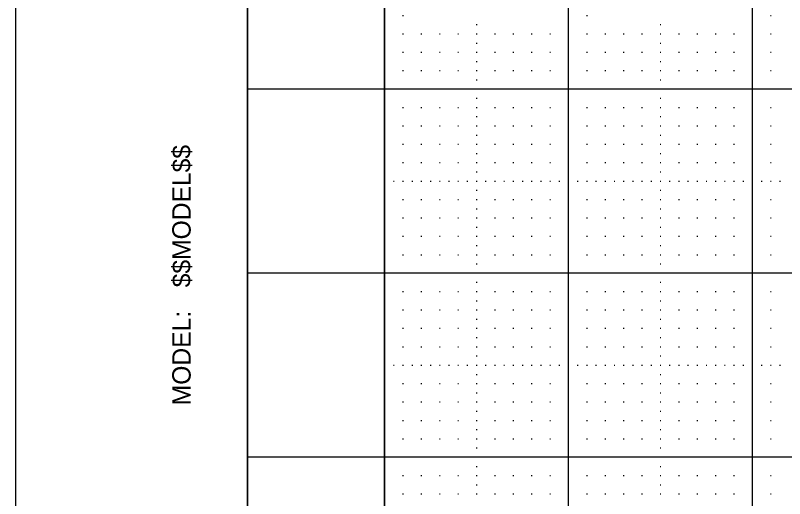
# Model space of a CAD drawing. Extents: x -1.3 to 32.1, y -0.2 to 20.7.
# Drawn here: x -1.263 to 2.92, y 5.068 to 7.693 of the extents above; entities that cross this region are included whole.
import ezdxf

# ---------------------------------------------------------------- set-up
doc = ezdxf.new("R2010")
doc.units = 0
for name, color, linetype in [('Level 1', 7, 'Continuous'), ('Level 37', 7, 'Continuous'), ('Level 4', 7, 'Continuous'), ('Level 5', 7, 'Continuous'), ('Level 62', 7, 'Continuous'), ('Level 63', 7, 'Continuous')]:
    doc.layers.add(name, color=color, linetype=linetype)

msp = doc.modelspace()

# ---------------------------------------------------------------- linework, layer by layer
at = {"layer": 'Level 1'}
msp.add_line((-0.001, -0.001), (-0.001, 20.545), dxfattribs=at)
at = {"layer": 'Level 37'}
msp.add_line((0.746, 0.6725), (0.746, 10.2935), dxfattribs=at)
at = {"layer": 'Level 4'}
for p, q in [((0.745, 0.672), (0.745, 10.293)), ((1.745, 0.672), (1.745, 10.293)), ((2.745, 0.293), (2.745, 10.293)), ((31.617, 7.293), (-0.001, 7.293)), ((31.617, 6.293), (-0.001, 6.293)), ((31.617, 5.293), (-0.001, 5.293))]:
    msp.add_line(p, q, dxfattribs=at)
at = {"layer": 'Level 5'}
for p, q in [((0.8425, 7.693), (0.8475, 7.693)), ((1.8425, 7.693), (1.8475, 7.693)), ((2.8425, 7.693), (2.8475, 7.693)), ((1.2425, 7.643), (1.2475, 7.643)), ((2.2425, 7.643), (2.2475, 7.643)), ((0.8425, 7.593), (0.8475, 7.593)), ((0.9425, 7.593), (0.9475, 7.593)), ((1.0425, 7.593), (1.0475, 7.593)), ((1.1425, 7.593), (1.1475, 7.593)), ((1.2425, 7.593), (1.2475, 7.593)), ((1.3425, 7.593), (1.3475, 7.593)), ((1.4425, 7.593), (1.4475, 7.593)), ((1.5425, 7.593), (1.5475, 7.593)), ((1.6425, 7.593), (1.6475, 7.593)), ((1.8425, 7.593), (1.8475, 7.593)), ((1.9425, 7.593), (1.9475, 7.593)), ((2.0425, 7.593), (2.0475, 7.593)), ((2.1425, 7.593), (2.1475, 7.593)), ((2.2425, 7.593), (2.2475, 7.593)), ((2.3425, 7.593), (2.3475, 7.593)), ((2.4425, 7.593), (2.4475, 7.593)), ((2.5425, 7.593), (2.5475, 7.593)), ((2.6425, 7.593), (2.6475, 7.593)), ((2.8425, 7.593), (2.8475, 7.593)), ((1.2425, 7.543), (1.2475, 7.543)), ((2.2425, 7.543), (2.2475, 7.543)), ((0.8425, 7.493), (0.8475, 7.493)), ((0.9425, 7.493), (0.9475, 7.493)), ((1.0425, 7.493), (1.0475, 7.493)), ((1.1425, 7.493), (1.1475, 7.493)), ((1.2425, 7.493), (1.2475, 7.493)), ((1.3425, 7.493), (1.3475, 7.493)), ((1.4425, 7.493), (1.4475, 7.493)), ((1.5425, 7.493), (1.5475, 7.493)), ((1.6425, 7.493), (1.6475, 7.493)), ((1.8425, 7.493), (1.8475, 7.493)), ((1.9425, 7.493), (1.9475, 7.493)), ((2.0425, 7.493), (2.0475, 7.493)), ((2.1425, 7.493), (2.1475, 7.493)), ((2.2425, 7.493), (2.2475, 7.493)), ((2.3425, 7.493), (2.3475, 7.493)), ((2.4425, 7.493), (2.4475, 7.493)), ((2.5425, 7.493), (2.5475, 7.493)), ((2.6425, 7.493), (2.6475, 7.493)), ((2.8425, 7.493), (2.8475, 7.493)), ((1.2425, 7.443), (1.2475, 7.443)), ((2.2425, 7.443), (2.2475, 7.443)), ((0.8425, 7.393), (0.8475, 7.393)), ((0.9425, 7.393), (0.9475, 7.393)), ((1.0425, 7.393), (1.0475, 7.393)), ((1.1425, 7.393), (1.1475, 7.393)), ((1.2425, 7.393), (1.2475, 7.393)), ((1.3425, 7.393), (1.3475, 7.393)), ((1.4425, 7.393), (1.4475, 7.393)), ((1.5425, 7.393), (1.5475, 7.393)), ((1.6425, 7.393), (1.6475, 7.393)), ((1.8425, 7.393), (1.8475, 7.393)), ((1.9425, 7.393), (1.9475, 7.393)), ((2.0425, 7.393), (2.0475, 7.393)), ((2.1425, 7.393), (2.1475, 7.393)), ((2.2425, 7.393), (2.2475, 7.393)), ((2.3425, 7.393), (2.3475, 7.393)), ((2.4425, 7.393), (2.4475, 7.393)), ((2.5425, 7.393), (2.5475, 7.393)), ((2.6425, 7.393), (2.6475, 7.393)), ((2.8425, 7.393), (2.8475, 7.393)), ((1.2425, 7.343), (1.2475, 7.343)), ((2.2425, 7.343), (2.2475, 7.343)), ((1.2425, 7.243), (1.2475, 7.243)), ((2.2425, 7.243), (2.2475, 7.243)), ((0.8425, 7.193), (0.8475, 7.193)), ((0.9425, 7.193), (0.9475, 7.193)), ((1.0425, 7.193), (1.0475, 7.193)), ((1.1425, 7.193), (1.1475, 7.193)), ((1.2425, 7.193), (1.2475, 7.193)), ((1.3425, 7.193), (1.3475, 7.193)), ((1.4425, 7.193), (1.4475, 7.193)), ((1.5425, 7.193), (1.5475, 7.193)), ((1.6425, 7.193), (1.6475, 7.193)), ((1.8425, 7.193), (1.8475, 7.193)), ((1.9425, 7.193), (1.9475, 7.193)), ((2.0425, 7.193), (2.0475, 7.193)), ((2.1425, 7.193), (2.1475, 7.193)), ((2.2425, 7.193), (2.2475, 7.193)), ((2.3425, 7.193), (2.3475, 7.193)), ((2.4425, 7.193), (2.4475, 7.193)), ((2.5425, 7.193), (2.5475, 7.193)), ((2.6425, 7.193), (2.6475, 7.193)), ((2.8425, 7.193), (2.8475, 7.193)), ((1.2425, 7.143), (1.2475, 7.143)), ((2.2425, 7.143), (2.2475, 7.143)), ((0.8425, 7.093), (0.8475, 7.093)), ((0.9425, 7.093), (0.9475, 7.093)), ((1.0425, 7.093), (1.0475, 7.093)), ((1.1425, 7.093), (1.1475, 7.093)), ((1.2425, 7.093), (1.2475, 7.093)), ((1.3425, 7.093), (1.3475, 7.093)), ((1.4425, 7.093), (1.4475, 7.093)), ((1.5425, 7.093), (1.5475, 7.093)), ((1.6425, 7.093), (1.6475, 7.093)), ((1.8425, 7.093), (1.8475, 7.093)), ((1.9425, 7.093), (1.9475, 7.093)), ((2.0425, 7.093), (2.0475, 7.093)), ((2.1425, 7.093), (2.1475, 7.093)), ((2.2425, 7.093), (2.2475, 7.093)), ((2.3425, 7.093), (2.3475, 7.093)), ((2.4425, 7.093), (2.4475, 7.093)), ((2.5425, 7.093), (2.5475, 7.093)), ((2.6425, 7.093), (2.6475, 7.093)), ((2.8425, 7.093), (2.8475, 7.093)), ((1.2425, 7.043), (1.2475, 7.043)), ((2.2425, 7.043), (2.2475, 7.043)), ((0.8425, 6.993), (0.8475, 6.993)), ((0.9425, 6.993), (0.9475, 6.993)), ((1.0425, 6.993), (1.0475, 6.993)), ((1.1425, 6.993), (1.1475, 6.993)), ((1.2425, 6.993), (1.2475, 6.993)), ((1.3425, 6.993), (1.3475, 6.993)), ((1.4425, 6.993), (1.4475, 6.993)), ((1.5425, 6.993), (1.5475, 6.993)), ((1.6425, 6.993), (1.6475, 6.993)), ((1.8425, 6.993), (1.8475, 6.993)), ((1.9425, 6.993), (1.9475, 6.993)), ((2.0425, 6.993), (2.0475, 6.993)), ((2.1425, 6.993), (2.1475, 6.993)), ((2.2425, 6.993), (2.2475, 6.993)), ((2.3425, 6.993), (2.3475, 6.993)), ((2.4425, 6.993), (2.4475, 6.993)), ((2.5425, 6.993), (2.5475, 6.993)), ((2.6425, 6.993), (2.6475, 6.993)), ((2.8425, 6.993), (2.8475, 6.993)), ((1.2425, 6.943), (1.2475, 6.943)), ((2.2425, 6.943), (2.2475, 6.943)), ((0.8425, 6.893), (0.8475, 6.893)), ((0.9425, 6.893), (0.9475, 6.893)), ((1.0425, 6.893), (1.0475, 6.893)), ((1.1425, 6.893), (1.1475, 6.893)), ((1.2425, 6.893), (1.2475, 6.893)), ((1.3425, 6.893), (1.3475, 6.893)), ((1.4425, 6.893), (1.4475, 6.893)), ((1.5425, 6.893), (1.5475, 6.893)), ((1.6425, 6.893), (1.6475, 6.893)), ((1.8425, 6.893), (1.8475, 6.893)), ((1.9425, 6.893), (1.9475, 6.893)), ((2.0425, 6.893), (2.0475, 6.893)), ((2.1425, 6.893), (2.1475, 6.893)), ((2.2425, 6.893), (2.2475, 6.893)), ((2.3425, 6.893), (2.3475, 6.893)), ((2.4425, 6.893), (2.4475, 6.893)), ((2.5425, 6.893), (2.5475, 6.893)), ((2.6425, 6.893), (2.6475, 6.893)), ((2.8425, 6.893), (2.8475, 6.893)), ((1.2425, 6.843), (1.2475, 6.843)), ((2.2425, 6.843), (2.2475, 6.843)), ((0.7925, 6.793), (0.7975, 6.793)), ((0.8425, 6.793), (0.8475, 6.793)), ((0.8925, 6.793), (0.8975, 6.793)), ((0.9425, 6.793), (0.9475, 6.793)), ((0.9925, 6.793), (0.9975, 6.793)), ((1.0425, 6.793), (1.0475, 6.793)), ((1.0925, 6.793), (1.0975, 6.793)), ((1.1425, 6.793), (1.1475, 6.793)), ((1.1925, 6.793), (1.1975, 6.793)), ((1.2425, 6.793), (1.2475, 6.793)), ((1.2925, 6.793), (1.2975, 6.793)), ((1.3425, 6.793), (1.3475, 6.793)), ((1.3925, 6.793), (1.3975, 6.793)), ((1.4425, 6.793), (1.4475, 6.793)), ((1.4925, 6.793), (1.4975, 6.793)), ((1.5425, 6.793), (1.5475, 6.793)), ((1.5925, 6.793), (1.5975, 6.793)), ((1.6425, 6.793), (1.6475, 6.793)), ((1.6925, 6.793), (1.6975, 6.793)), ((1.7925, 6.793), (1.7975, 6.793)), ((1.8425, 6.793), (1.8475, 6.793)), ((1.8925, 6.793), (1.8975, 6.793)), ((1.9425, 6.793), (1.9475, 6.793)), ((1.9925, 6.793), (1.9975, 6.793)), ((2.0425, 6.793), (2.0475, 6.793)), ((2.0925, 6.793), (2.0975, 6.793)), ((2.1425, 6.793), (2.1475, 6.793)), ((2.1925, 6.793), (2.1975, 6.793)), ((2.2425, 6.793), (2.2475, 6.793)), ((2.2925, 6.793), (2.2975, 6.793)), ((2.3425, 6.793), (2.3475, 6.793)), ((2.3925, 6.793), (2.3975, 6.793)), ((2.4425, 6.793), (2.4475, 6.793)), ((2.4925, 6.793), (2.4975, 6.793)), ((2.5425, 6.793), (2.5475, 6.793)), ((2.5925, 6.793), (2.5975, 6.793)), ((2.6425, 6.793), (2.6475, 6.793)), ((2.6925, 6.793), (2.6975, 6.793)), ((2.7925, 6.793), (2.7975, 6.793)), ((2.8425, 6.793), (2.8475, 6.793)), ((2.8925, 6.793), (2.8975, 6.793)), ((1.2425, 6.743), (1.2475, 6.743)), ((2.2425, 6.743), (2.2475, 6.743)), ((0.8425, 6.693), (0.8475, 6.693)), ((0.9425, 6.693), (0.9475, 6.693)), ((1.0425, 6.693), (1.0475, 6.693)), ((1.1425, 6.693), (1.1475, 6.693)), ((1.2425, 6.693), (1.2475, 6.693)), ((1.3425, 6.693), (1.3475, 6.693)), ((1.4425, 6.693), (1.4475, 6.693)), ((1.5425, 6.693), (1.5475, 6.693)), ((1.6425, 6.693), (1.6475, 6.693)), ((1.8425, 6.693), (1.8475, 6.693)), ((1.9425, 6.693), (1.9475, 6.693)), ((2.0425, 6.693), (2.0475, 6.693)), ((2.1425, 6.693), (2.1475, 6.693)), ((2.2425, 6.693), (2.2475, 6.693)), ((2.3425, 6.693), (2.3475, 6.693)), ((2.4425, 6.693), (2.4475, 6.693)), ((2.5425, 6.693), (2.5475, 6.693)), ((2.6425, 6.693), (2.6475, 6.693)), ((2.8425, 6.693), (2.8475, 6.693)), ((1.2425, 6.643), (1.2475, 6.643)), ((2.2425, 6.643), (2.2475, 6.643)), ((0.8425, 6.593), (0.8475, 6.593)), ((0.9425, 6.593), (0.9475, 6.593)), ((1.0425, 6.593), (1.0475, 6.593)), ((1.1425, 6.593), (1.1475, 6.593)), ((1.2425, 6.593), (1.2475, 6.593)), ((1.3425, 6.593), (1.3475, 6.593)), ((1.4425, 6.593), (1.4475, 6.593)), ((1.5425, 6.593), (1.5475, 6.593)), ((1.6425, 6.593), (1.6475, 6.593)), ((1.8425, 6.593), (1.8475, 6.593)), ((1.9425, 6.593), (1.9475, 6.593)), ((2.0425, 6.593), (2.0475, 6.593)), ((2.1425, 6.593), (2.1475, 6.593)), ((2.2425, 6.593), (2.2475, 6.593)), ((2.3425, 6.593), (2.3475, 6.593)), ((2.4425, 6.593), (2.4475, 6.593)), ((2.5425, 6.593), (2.5475, 6.593)), ((2.6425, 6.593), (2.6475, 6.593)), ((2.8425, 6.593), (2.8475, 6.593)), ((1.2425, 6.543), (1.2475, 6.543)), ((2.2425, 6.543), (2.2475, 6.543)), ((0.8425, 6.493), (0.8475, 6.493)), ((0.9425, 6.493), (0.9475, 6.493)), ((1.0425, 6.493), (1.0475, 6.493)), ((1.1425, 6.493), (1.1475, 6.493)), ((1.2425, 6.493), (1.2475, 6.493)), ((1.3425, 6.493), (1.3475, 6.493)), ((1.4425, 6.493), (1.4475, 6.493)), ((1.5425, 6.493), (1.5475, 6.493)), ((1.6425, 6.493), (1.6475, 6.493)), ((1.8425, 6.493), (1.8475, 6.493)), ((1.9425, 6.493), (1.9475, 6.493)), ((2.0425, 6.493), (2.0475, 6.493)), ((2.1425, 6.493), (2.1475, 6.493)), ((2.2425, 6.493), (2.2475, 6.493)), ((2.3425, 6.493), (2.3475, 6.493)), ((2.4425, 6.493), (2.4475, 6.493)), ((2.5425, 6.493), (2.5475, 6.493)), ((2.6425, 6.493), (2.6475, 6.493)), ((2.8425, 6.493), (2.8475, 6.493)), ((1.2425, 6.443), (1.2475, 6.443)), ((2.2425, 6.443), (2.2475, 6.443)), ((0.8425, 6.393), (0.8475, 6.393)), ((0.9425, 6.393), (0.9475, 6.393)), ((1.0425, 6.393), (1.0475, 6.393)), ((1.1425, 6.393), (1.1475, 6.393)), ((1.2425, 6.393), (1.2475, 6.393)), ((1.3425, 6.393), (1.3475, 6.393)), ((1.4425, 6.393), (1.4475, 6.393)), ((1.5425, 6.393), (1.5475, 6.393)), ((1.6425, 6.393), (1.6475, 6.393)), ((1.8425, 6.393), (1.8475, 6.393)), ((1.9425, 6.393), (1.9475, 6.393)), ((2.0425, 6.393), (2.0475, 6.393)), ((2.1425, 6.393), (2.1475, 6.393)), ((2.2425, 6.393), (2.2475, 6.393)), ((2.3425, 6.393), (2.3475, 6.393)), ((2.4425, 6.393), (2.4475, 6.393)), ((2.5425, 6.393), (2.5475, 6.393)), ((2.6425, 6.393), (2.6475, 6.393)), ((2.8425, 6.393), (2.8475, 6.393)), ((1.2425, 6.343), (1.2475, 6.343)), ((2.2425, 6.343), (2.2475, 6.343)), ((1.2425, 6.243), (1.2475, 6.243)), ((2.2425, 6.243), (2.2475, 6.243)), ((0.8425, 6.193), (0.8475, 6.193)), ((0.9425, 6.193), (0.9475, 6.193)), ((1.0425, 6.193), (1.0475, 6.193)), ((1.1425, 6.193), (1.1475, 6.193)), ((1.2425, 6.193), (1.2475, 6.193)), ((1.3425, 6.193), (1.3475, 6.193)), ((1.4425, 6.193), (1.4475, 6.193)), ((1.5425, 6.193), (1.5475, 6.193)), ((1.6425, 6.193), (1.6475, 6.193)), ((1.8425, 6.193), (1.8475, 6.193)), ((1.9425, 6.193), (1.9475, 6.193)), ((2.0425, 6.193), (2.0475, 6.193)), ((2.1425, 6.193), (2.1475, 6.193)), ((2.2425, 6.193), (2.2475, 6.193)), ((2.3425, 6.193), (2.3475, 6.193)), ((2.4425, 6.193), (2.4475, 6.193)), ((2.5425, 6.193), (2.5475, 6.193)), ((2.6425, 6.193), (2.6475, 6.193)), ((2.8425, 6.193), (2.8475, 6.193)), ((1.2425, 6.143), (1.2475, 6.143)), ((2.2425, 6.143), (2.2475, 6.143)), ((0.8425, 6.093), (0.8475, 6.093)), ((0.9425, 6.093), (0.9475, 6.093)), ((1.0425, 6.093), (1.0475, 6.093)), ((1.1425, 6.093), (1.1475, 6.093)), ((1.2425, 6.093), (1.2475, 6.093)), ((1.3425, 6.093), (1.3475, 6.093)), ((1.4425, 6.093), (1.4475, 6.093)), ((1.5425, 6.093), (1.5475, 6.093)), ((1.6425, 6.093), (1.6475, 6.093)), ((1.8425, 6.093), (1.8475, 6.093)), ((1.9425, 6.093), (1.9475, 6.093)), ((2.0425, 6.093), (2.0475, 6.093)), ((2.1425, 6.093), (2.1475, 6.093)), ((2.2425, 6.093), (2.2475, 6.093)), ((2.3425, 6.093), (2.3475, 6.093)), ((2.4425, 6.093), (2.4475, 6.093)), ((2.5425, 6.093), (2.5475, 6.093)), ((2.6425, 6.093), (2.6475, 6.093)), ((2.8425, 6.093), (2.8475, 6.093)), ((1.2425, 6.043), (1.2475, 6.043)), ((2.2425, 6.043), (2.2475, 6.043)), ((0.8425, 5.993), (0.8475, 5.993)), ((0.9425, 5.993), (0.9475, 5.993)), ((1.0425, 5.993), (1.0475, 5.993)), ((1.1425, 5.993), (1.1475, 5.993)), ((1.2425, 5.993), (1.2475, 5.993)), ((1.3425, 5.993), (1.3475, 5.993)), ((1.4425, 5.993), (1.4475, 5.993)), ((1.5425, 5.993), (1.5475, 5.993)), ((1.6425, 5.993), (1.6475, 5.993)), ((1.8425, 5.993), (1.8475, 5.993)), ((1.9425, 5.993), (1.9475, 5.993)), ((2.0425, 5.993), (2.0475, 5.993)), ((2.1425, 5.993), (2.1475, 5.993)), ((2.2425, 5.993), (2.2475, 5.993)), ((2.3425, 5.993), (2.3475, 5.993)), ((2.4425, 5.993), (2.4475, 5.993)), ((2.5425, 5.993), (2.5475, 5.993)), ((2.6425, 5.993), (2.6475, 5.993)), ((2.8425, 5.993), (2.8475, 5.993)), ((1.2425, 5.943), (1.2475, 5.943)), ((2.2425, 5.943), (2.2475, 5.943)), ((0.8425, 5.893), (0.8475, 5.893)), ((0.9425, 5.893), (0.9475, 5.893)), ((1.0425, 5.893), (1.0475, 5.893)), ((1.1425, 5.893), (1.1475, 5.893)), ((1.2425, 5.893), (1.2475, 5.893)), ((1.3425, 5.893), (1.3475, 5.893)), ((1.4425, 5.893), (1.4475, 5.893)), ((1.5425, 5.893), (1.5475, 5.893)), ((1.6425, 5.893), (1.6475, 5.893)), ((1.8425, 5.893), (1.8475, 5.893)), ((1.9425, 5.893), (1.9475, 5.893)), ((2.0425, 5.893), (2.0475, 5.893)), ((2.1425, 5.893), (2.1475, 5.893)), ((2.2425, 5.893), (2.2475, 5.893)), ((2.3425, 5.893), (2.3475, 5.893)), ((2.4425, 5.893), (2.4475, 5.893)), ((2.5425, 5.893), (2.5475, 5.893)), ((2.6425, 5.893), (2.6475, 5.893)), ((2.8425, 5.893), (2.8475, 5.893)), ((1.2425, 5.843), (1.2475, 5.843)), ((2.2425, 5.843), (2.2475, 5.843)), ((0.7925, 5.793), (0.7975, 5.793)), ((0.8425, 5.793), (0.8475, 5.793)), ((0.8925, 5.793), (0.8975, 5.793)), ((0.9425, 5.793), (0.9475, 5.793)), ((0.9925, 5.793), (0.9975, 5.793)), ((1.0425, 5.793), (1.0475, 5.793)), ((1.0925, 5.793), (1.0975, 5.793)), ((1.1425, 5.793), (1.1475, 5.793)), ((1.1925, 5.793), (1.1975, 5.793)), ((1.2425, 5.793), (1.2475, 5.793)), ((1.2925, 5.793), (1.2975, 5.793)), ((1.3425, 5.793), (1.3475, 5.793)), ((1.3925, 5.793), (1.3975, 5.793)), ((1.4425, 5.793), (1.4475, 5.793)), ((1.4925, 5.793), (1.4975, 5.793)), ((1.5425, 5.793), (1.5475, 5.793)), ((1.5925, 5.793), (1.5975, 5.793)), ((1.6425, 5.793), (1.6475, 5.793)), ((1.6925, 5.793), (1.6975, 5.793)), ((1.7925, 5.793), (1.7975, 5.793)), ((1.8425, 5.793), (1.8475, 5.793)), ((1.8925, 5.793), (1.8975, 5.793)), ((1.9425, 5.793), (1.9475, 5.793)), ((1.9925, 5.793), (1.9975, 5.793)), ((2.0425, 5.793), (2.0475, 5.793)), ((2.0925, 5.793), (2.0975, 5.793)), ((2.1425, 5.793), (2.1475, 5.793)), ((2.1925, 5.793), (2.1975, 5.793)), ((2.2425, 5.793), (2.2475, 5.793)), ((2.2925, 5.793), (2.2975, 5.793)), ((2.3425, 5.793), (2.3475, 5.793)), ((2.3925, 5.793), (2.3975, 5.793)), ((2.4425, 5.793), (2.4475, 5.793)), ((2.4925, 5.793), (2.4975, 5.793)), ((2.5425, 5.793), (2.5475, 5.793)), ((2.5925, 5.793), (2.5975, 5.793)), ((2.6425, 5.793), (2.6475, 5.793)), ((2.6925, 5.793), (2.6975, 5.793)), ((2.7925, 5.793), (2.7975, 5.793)), ((2.8425, 5.793), (2.8475, 5.793)), ((2.8925, 5.793), (2.8975, 5.793)), ((1.2425, 5.743), (1.2475, 5.743)), ((2.2425, 5.743), (2.2475, 5.743)), ((0.8425, 5.693), (0.8475, 5.693)), ((0.9425, 5.693), (0.9475, 5.693)), ((1.0425, 5.693), (1.0475, 5.693)), ((1.1425, 5.693), (1.1475, 5.693)), ((1.2425, 5.693), (1.2475, 5.693)), ((1.3425, 5.693), (1.3475, 5.693)), ((1.4425, 5.693), (1.4475, 5.693)), ((1.5425, 5.693), (1.5475, 5.693)), ((1.6425, 5.693), (1.6475, 5.693)), ((1.8425, 5.693), (1.8475, 5.693)), ((1.9425, 5.693), (1.9475, 5.693)), ((2.0425, 5.693), (2.0475, 5.693)), ((2.1425, 5.693), (2.1475, 5.693)), ((2.2425, 5.693), (2.2475, 5.693)), ((2.3425, 5.693), (2.3475, 5.693)), ((2.4425, 5.693), (2.4475, 5.693)), ((2.5425, 5.693), (2.5475, 5.693)), ((2.6425, 5.693), (2.6475, 5.693)), ((2.8425, 5.693), (2.8475, 5.693)), ((1.2425, 5.643), (1.2475, 5.643)), ((2.2425, 5.643), (2.2475, 5.643)), ((0.8425, 5.593), (0.8475, 5.593)), ((0.9425, 5.593), (0.9475, 5.593)), ((1.0425, 5.593), (1.0475, 5.593)), ((1.1425, 5.593), (1.1475, 5.593)), ((1.2425, 5.593), (1.2475, 5.593)), ((1.3425, 5.593), (1.3475, 5.593)), ((1.4425, 5.593), (1.4475, 5.593)), ((1.5425, 5.593), (1.5475, 5.593)), ((1.6425, 5.593), (1.6475, 5.593)), ((1.8425, 5.593), (1.8475, 5.593)), ((1.9425, 5.593), (1.9475, 5.593)), ((2.0425, 5.593), (2.0475, 5.593)), ((2.1425, 5.593), (2.1475, 5.593)), ((2.2425, 5.593), (2.2475, 5.593)), ((2.3425, 5.593), (2.3475, 5.593)), ((2.4425, 5.593), (2.4475, 5.593)), ((2.5425, 5.593), (2.5475, 5.593)), ((2.6425, 5.593), (2.6475, 5.593)), ((2.8425, 5.593), (2.8475, 5.593)), ((1.2425, 5.543), (1.2475, 5.543)), ((2.2425, 5.543), (2.2475, 5.543)), ((0.8425, 5.493), (0.8475, 5.493)), ((0.9425, 5.493), (0.9475, 5.493)), ((1.0425, 5.493), (1.0475, 5.493)), ((1.1425, 5.493), (1.1475, 5.493)), ((1.2425, 5.493), (1.2475, 5.493)), ((1.3425, 5.493), (1.3475, 5.493)), ((1.4425, 5.493), (1.4475, 5.493)), ((1.5425, 5.493), (1.5475, 5.493)), ((1.6425, 5.493), (1.6475, 5.493)), ((1.8425, 5.493), (1.8475, 5.493)), ((1.9425, 5.493), (1.9475, 5.493)), ((2.0425, 5.493), (2.0475, 5.493)), ((2.1425, 5.493), (2.1475, 5.493)), ((2.2425, 5.493), (2.2475, 5.493)), ((2.3425, 5.493), (2.3475, 5.493)), ((2.4425, 5.493), (2.4475, 5.493)), ((2.5425, 5.493), (2.5475, 5.493)), ((2.6425, 5.493), (2.6475, 5.493)), ((2.8425, 5.493), (2.8475, 5.493)), ((1.2425, 5.443), (1.2475, 5.443)), ((2.2425, 5.443), (2.2475, 5.443)), ((0.8425, 5.393), (0.8475, 5.393)), ((0.9425, 5.393), (0.9475, 5.393)), ((1.0425, 5.393), (1.0475, 5.393)), ((1.1425, 5.393), (1.1475, 5.393)), ((1.2425, 5.393), (1.2475, 5.393)), ((1.3425, 5.393), (1.3475, 5.393)), ((1.4425, 5.393), (1.4475, 5.393)), ((1.5425, 5.393), (1.5475, 5.393)), ((1.6425, 5.393), (1.6475, 5.393)), ((1.8425, 5.393), (1.8475, 5.393)), ((1.9425, 5.393), (1.9475, 5.393)), ((2.0425, 5.393), (2.0475, 5.393)), ((2.1425, 5.393), (2.1475, 5.393)), ((2.2425, 5.393), (2.2475, 5.393)), ((2.3425, 5.393), (2.3475, 5.393)), ((2.4425, 5.393), (2.4475, 5.393)), ((2.5425, 5.393), (2.5475, 5.393)), ((2.6425, 5.393), (2.6475, 5.393)), ((2.8425, 5.393), (2.8475, 5.393)), ((1.2425, 5.343), (1.2475, 5.343)), ((2.2425, 5.343), (2.2475, 5.343)), ((1.2425, 5.243), (1.2475, 5.243)), ((2.2425, 5.243), (2.2475, 5.243)), ((0.8425, 5.193), (0.8475, 5.193)), ((0.9425, 5.193), (0.9475, 5.193)), ((1.0425, 5.193), (1.0475, 5.193)), ((1.1425, 5.193), (1.1475, 5.193)), ((1.2425, 5.193), (1.2475, 5.193)), ((1.3425, 5.193), (1.3475, 5.193)), ((1.4425, 5.193), (1.4475, 5.193)), ((1.5425, 5.193), (1.5475, 5.193)), ((1.6425, 5.193), (1.6475, 5.193)), ((1.8425, 5.193), (1.8475, 5.193)), ((1.9425, 5.193), (1.9475, 5.193)), ((2.0425, 5.193), (2.0475, 5.193)), ((2.1425, 5.193), (2.1475, 5.193)), ((2.2425, 5.193), (2.2475, 5.193)), ((2.3425, 5.193), (2.3475, 5.193)), ((2.4425, 5.193), (2.4475, 5.193)), ((2.5425, 5.193), (2.5475, 5.193)), ((2.6425, 5.193), (2.6475, 5.193)), ((2.8425, 5.193), (2.8475, 5.193)), ((1.2425, 5.143), (1.2475, 5.143)), ((2.2425, 5.143), (2.2475, 5.143)), ((0.8425, 5.093), (0.8475, 5.093)), ((0.9425, 5.093), (0.9475, 5.093)), ((1.0425, 5.093), (1.0475, 5.093)), ((1.1425, 5.093), (1.1475, 5.093)), ((1.2425, 5.093), (1.2475, 5.093)), ((1.3425, 5.093), (1.3475, 5.093)), ((1.4425, 5.093), (1.4475, 5.093)), ((1.5425, 5.093), (1.5475, 5.093)), ((1.6425, 5.093), (1.6475, 5.093)), ((1.8425, 5.093), (1.8475, 5.093)), ((1.9425, 5.093), (1.9475, 5.093)), ((2.0425, 5.093), (2.0475, 5.093)), ((2.1425, 5.093), (2.1475, 5.093)), ((2.2425, 5.093), (2.2475, 5.093)), ((2.3425, 5.093), (2.3475, 5.093)), ((2.4425, 5.093), (2.4475, 5.093)), ((2.5425, 5.093), (2.5475, 5.093)), ((2.6425, 5.093), (2.6475, 5.093)), ((2.8425, 5.093), (2.8475, 5.093))]:
    msp.add_line(p, q, dxfattribs=at)
at = {"layer": 'Level 62'}
msp.add_line((0, 10.294), (0, 0.6734), dxfattribs=at)
at = {"layer": 'Level 63'}
msp.add_lwpolyline([(-1.263, -0.2005), (32.067, -0.2005), (32.067, 20.7465), (-1.263, 20.7465)], close=True, dxfattribs=at)

# ---------------------------------------------------------------- texts
at = {"layer": 'Level 1'}
for s, p in [('$$MODEL$$', (-0.31, 6.216)), ('MODEL:', (-0.31, 5.575))]:
    msp.add_text(s, height=0.1, rotation=90, dxfattribs=at).set_placement(p)

doc.saveas('drawing.dxf')
